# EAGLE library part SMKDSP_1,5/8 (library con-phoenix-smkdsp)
Printklemme, Nennstrom: 17,5 A, Bemessungsspannung: 250 V, Raster: 5,0 mm Source: http://eshop.phoenixcontact.de .. 1733415.pdf
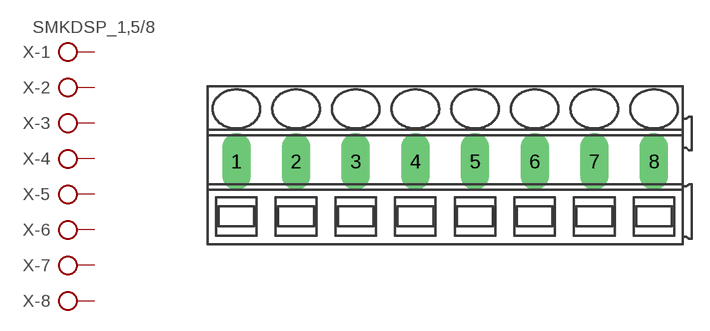
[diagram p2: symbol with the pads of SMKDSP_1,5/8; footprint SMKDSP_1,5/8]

Designator prefix X; gates -1=KLV -2=KL -3=KL -4=KL -5=KL -6=KL -7=KL -8=KL

## SMKDSP_1,5/8 (MF: FARNELL; MPN: 1733635; OC_FARNELL: 3041281; OC_NEWARK: 71C4133)  [SMKDSP_1,5/8]
1  -1:KL  pas
2  -2:KL  pas
3  -3:KL  pas
4  -4:KL  pas
5  -5:KL  pas
6  -6:KL  pas
7  -7:KL  pas
8  -8:KL  pas

## Footprint SMKDSP_1,5/8 (pad centres in mm)
Printklemme, Nennstrom: 17,5 A, Bemessungsspannung: 250 V, Raster: 5,0 mm Source: http://eshop.phoenixcontact.de .. 1733415.pdf
drill 1.6 pad 1.8 long: 1 -2.5,0; 2 2.5,0; 3 7.5,0; 4 12.5,0; 5 17.5,0; 6 22.5,0; 7 27.5,0; 8 32.5,0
